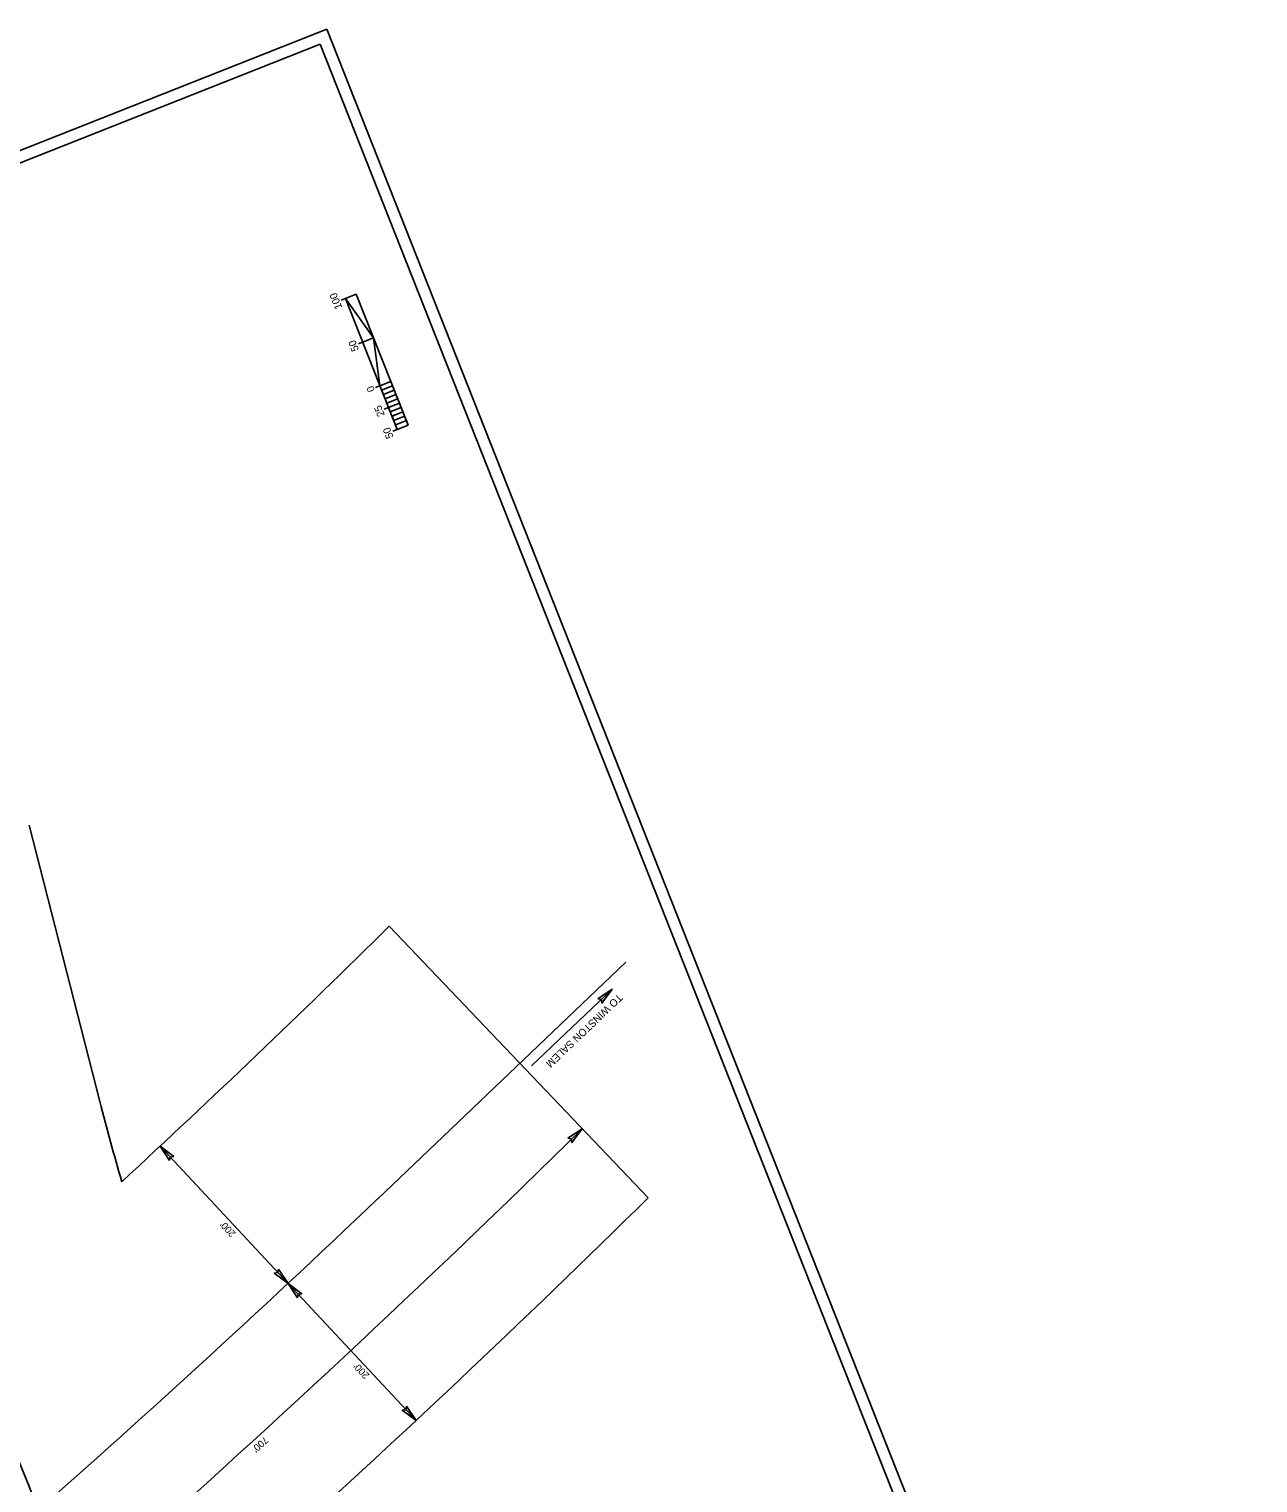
# Model space of a CAD drawing. Extents: x 1550555 to 1553129, y 809174 to 812311.
# Drawn here: x 1551819 to 1553129, y 810761 to 812311 of the extents above; entities that cross this region are included whole.
import ezdxf

# ---------------------------------------------------------------- set-up
doc = ezdxf.new("R2010")
doc.units = 0
for name, color, linetype in [('Old_Level_1', 7, 'Continuous'), ('P_RDY_Dimension', 7, 'Continuous'), ('P_RDY_Dimension_Text', 7, 'Continuous'), ('P_RDY_Terminator_Cell', 7, 'Continuous'), ('Pattern_4', 7, 'Continuous'), ('Site_Temp_Construction', 7, 'Continuous')]:
    doc.layers.add(name, color=color, linetype=linetype)

msp = doc.modelspace()

# ---------------------------------------------------------------- linework, layer by layer
at = {"layer": 'Old_Level_1'}
for points in [[(1552136.2, 812311.3), (1553129.1, 809800.4), (1551548.3, 809175.3), (1550555.4, 811686.1)], [(1552129.2, 812295), (1553112.9, 809807.5), (1551555.3, 809191.5), (1550571.6, 811679.1)]]:
    msp.add_lwpolyline(points, close=True, dxfattribs=at)
at = {"layer": 'P_RDY_Dimension'}
for p, q in [((1551958.4, 811120.2), (1552094.9, 810974)), ((1552094.9, 810974), (1552231.4, 810827.8))]:
    msp.add_line(p, q, dxfattribs=at)
msp.add_arc((1543473.3, 820207.4), 12730.9, 311.40768, 314.57582, dxfattribs=at)
at = {"layer": 'P_RDY_Terminator_Cell'}
for points in [[(1552425.3, 811277.5), (1552440.5, 811287.7), (1552429.6, 811272.9), (1552429, 811276.8)], [(1552393.3, 811128.8), (1552408.5, 811138.9), (1552397.6, 811124.1), (1552397, 811128)], [(1551968.4, 811104.9), (1551958.4, 811120.2), (1551973.1, 811109.1), (1551969.2, 811108.6)], [(1552084.9, 810989.2), (1552094.9, 810974), (1552080.2, 810985), (1552084.1, 810985.5)], [(1552104.9, 810958.7), (1552094.9, 810974), (1552109.6, 810962.9), (1552105.7, 810962.4)], [(1552221.4, 810843.1), (1552231.4, 810827.8), (1552216.7, 810838.8), (1552220.6, 810839.3)]]:
    msp.add_lwpolyline(points, close=True, dxfattribs=at)
at = {"layer": 'Pattern_4'}
msp.add_line((1552455.1, 811316.4), (1552190.2, 811063.9), dxfattribs=at)
for centre, radius, start, end in [((1554498, 811834.5), 2887.7, 194.3637, 209.2123), ((1543473.3, 820207.4), 12632.8, 308.90318, 313.63201)]:
    msp.add_arc(centre, radius, start, end, dxfattribs=at)
at = {"layer": 'Site_Temp_Construction'}
for p, q in [((1552167.7, 812028.6), (1552151.5, 812022.2)), ((1552186.1, 811982.1), (1552169.9, 811975.7)), ((1552204.5, 811935.6), (1552188.2, 811929.2)), ((1552204.5, 811935.6), (1552192.9, 811931)), ((1552206.4, 811931), (1552194.7, 811926.4)), ((1552208.2, 811926.3), (1552196.6, 811921.7)), ((1552213.7, 811912.4), (1552197.4, 811905.9)), ((1552210, 811921.7), (1552198.4, 811917.1)), ((1552211.9, 811917), (1552200.2, 811912.4)), ((1552213.7, 811912.4), (1552202.1, 811907.8)), ((1552215.5, 811907.7), (1552203.9, 811903.1)), ((1552217.4, 811903.1), (1552205.8, 811898.5)), ((1552219.2, 811898.4), (1552207.6, 811893.8)), ((1552222.9, 811889.1), (1552206.6, 811882.7)), ((1552221.1, 811893.8), (1552209.4, 811889.2)), ((1551894.3, 811167.8), (1551818.8, 811462.5)), ((1552202.8, 811354.7), (1552478.8, 811065.1)), ((1552440.5, 811287.7), (1552354.7, 811205.9))]:
    msp.add_line(p, q, dxfattribs=at)
for points in [[(1552222.9, 811889.1), (1552167.7, 812028.6), (1552156.1, 812024), (1552211.3, 811884.5)], [(1552186.1, 811982.1), (1552156.1, 812024), (1552167.7, 812028.6)], [(1552204.5, 811935.6), (1552192.9, 811931), (1552186.1, 811982.1)], [(1552194.7, 811926.4), (1552206.4, 811931), (1552208.2, 811926.3), (1552196.6, 811921.7)], [(1552198.4, 811917.1), (1552210, 811921.7), (1552211.9, 811917), (1552200.2, 811912.4)], [(1552202.1, 811907.8), (1552213.7, 811912.4), (1552215.5, 811907.7), (1552203.9, 811903.1)], [(1552205.8, 811898.5), (1552217.4, 811903.1), (1552219.2, 811898.4), (1552207.6, 811893.8)], [(1552222.9, 811889.1), (1552211.3, 811884.5), (1552209.4, 811889.2), (1552221.1, 811893.8)]]:
    msp.add_lwpolyline(points, close=True, dxfattribs=at)
for centre, radius, start, end in [((1543473.3, 820207.4), 12432.8, 312.78114, 314.59844), ((1554498, 811834.5), 2687.7, 194.3637, 196.2531), ((1543473.3, 820207.4), 12832.8, 312.06361, 314.56831)]:
    msp.add_arc(centre, radius, start, end, dxfattribs=at)

# ---------------------------------------------------------------- texts
at = {"layer": 'P_RDY_Dimension_Text'}
for s, height, rotation, p in [('TO WINSTON SALEM', 8, 223.632, (1552447.1, 811283.3)), ("200'", 7.5, 133.0374, (1552039.7, 811027.6)), ("200'", 7.5, 133.0374, (1552182.2, 810876.4)), ("700'", 7.5, 222.2577, (1552069.8, 810811.2))]:
    msp.add_text(s, height=height, rotation=rotation, dxfattribs=at).set_placement(p)
at = {"layer": 'Site_Temp_Construction'}
for s, p in [('100', (1552152.9, 812014.3)), ('50', (1552170.7, 811969.4)), ('0', (1552187.8, 811926.2)), ('25', (1552198.2, 811899.9)), ('50', (1552207.5, 811876.4))]:
    msp.add_text(s, height=8, rotation=111.5761, dxfattribs=at).set_placement(p)

doc.saveas('drawing.dxf')
